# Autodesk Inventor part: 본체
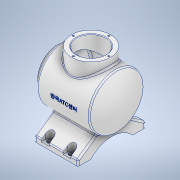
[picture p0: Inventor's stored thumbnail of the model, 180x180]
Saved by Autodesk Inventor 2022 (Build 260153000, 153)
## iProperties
Created: 2023-04
Part Number: 본체
Material: 알루미늄 6061
Document SubType Name: Modeling
Designer: Admin
Mass: 1296.71 g
Surface Area: 1060.44 cm^2
Volume: 480.263 cm^3
Density: 2.7 g/cm^3
Appearance: 알루미늄 - 평지
Author: Admin
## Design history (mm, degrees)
sketch "스케치1"
  geometry: L1 (-84.575, 0)-(87.453, 0) reference; L2 (0, -24.969)-(0, 149.813) reference; L3 (-60, 0)-(-60, 36); L4 (-60, 36)-(-48, 36); L5 (-48, 36)-(-48, 50); L6 (-48, 50)-(48.336, 50); L7 (60, 0)-(60, 124.844); L8 (-60, 0)-(60, 0); A1 r 113 centre (-53, 0) between (60, 0) and (48.336, 50); 1 further point
  constraints: 12 end point, 2 perpendicular, 2 point on circle, 2 point on line, 2 vertical, 1 centre point, 1 collinear, 1 horizontal, 1 tangent, 1 other
  dimensions: "d2" = 226 diameter of A1; "d3" = 120 distance from line of L7.start L3; "d4" = 108 distance from line of L7.start L5; "d5" = 72 diameter of L4 L1; "d6" = 100 diameter of L6 L1
revolve "회전1" sketch "스케치1" stored, may be unused: angle "d7" = 90 deg
node "작업 평면1"
sketch "스케치2"
  geometry: L1 (-38.5, -77)-(-62, -77); L2 (-62, -77)-(-62, -67); L3 (-62, -67)-(-15.04, -34.118); L4 (0, -144.515)-(0, 82.419) reference; L5 (62, -67)-(15.04, -34.118); L6 (62, -77)-(62, -67); L7 (38.5, -77)-(62, -77); L8 (-19.186, -60)-(22.433, -60); L9 (-86.8, 0)-(86.8, 0) reference; L10 (-15.04, -34.118)-(15.04, -34.118); A1 r 52.096 centre (0, -112.096) between (38.5, -77) and (-38.5, -77); 1 further point
  constraints: 16 end point, 4 symmetric about line, 3 horizontal, 2 point on circle, 1 centre point, 1 perpendicular, 1 tangent
  dimensions: "d9" = 10 distance of L1.end L2.end; "d10" = 77 distance of L7.start L1.start; "d11" = 55 deg angle of L6 L5; "d12" = 17 distance between parallel lines of L8 L7; "d13" = 124 distance between parallel lines of L6 L2; "d14" = 77 distance between parallel lines of L7 L9; "d15" = 42.88199 distance between parallel lines of L7 L10
extrude "돌출1" join sketch "스케치2" distance "d16" = 80; taper "d17" = 0 deg
node "작업 평면2"
sketch "스케치3"
  geometry: L1 (-44, -38.5)-(124, -38.5) reference; L2 (-20, -74.5)-(-20, -2.5) reference; C1 r 36 at (42, -38.5); 1 further point
  constraints: 1 centre point, 1 coincident, 1 point on line
  dimensions: "d19" = 72 diameter of C1; "d82" = 62 distance from line of point (42, -38.5) L2
extrude "돌출2" join sketch "스케치3" stored distance "d20" = 80; taper "d21" = 0 deg
sketch "스케치4"
  geometry: C1 r 36 at (0, 0) reference; C2 r 27 at (0, 0); 1 further point
  constraints: 1 centre point, 1 coincident
  dimensions: "d22" = 54 diameter of C2
extrude "돌출3" cut sketch "스케치4" distance "d23" = 60; taper "d24" = 0 deg
sketch "스케치5"
  geometry: L1 (-84, 0)-(84, 0) reference; L2 (-60, -36)-(-60, 36) reference; L3 (-60, 27)-(-41, 27); L4 (-41, 27)-(-41, 43); L5 (-41, 43)-(43.887, 43); L6 (-60, 27)-(-60, 0); L7 (-60, 0)-(53, 0); L8 (48.336, -50)-(48.336, 50) reference; A1 r 113 centre (-53, 0) between (48.336, -50) and (48.336, 50) reference; A2 r 106 centre (-53, 0) between (53, 0) and (43.887, 43); 1 further point
  constraints: 10 end point, 4 perpendicular, 2 point on circle, 2 point on line, 1 centre point, 1 midpoint
  dimensions: "d25" = 7 radial gap between concentric circles of A1 A2; "d26" = 54 diameter of L3 L1; "d27" = 19 distance of L3.start L3.end; "d28" = 86 diameter of L5 L1
revolve "회전2" sketch "스케치5" stored, may be unused: angle "d29" = 90 deg
node "작업 평면3"
sketch "스케치7"
  geometry: L1 (0, 0)-(80, 0) reference; L2 (0, 0)-(0, 23.5) reference; L3 (-44, 62)-(124, 62) reference; C1 r 4.5 at (20, 8); C2 r 4.5 at (60, 8); C3 r 4.5 at (20, 116); C4 r 4.5 at (60, 116); 1 further point
  constraints: 4 centre point, 2 symmetric about line, 2 other
  dimensions: "d37" = 8 distance from line of C1.centre L1; "d38" = 20 distance from line of C1.centre L2; "d39" = 9 diameter of C1; "d40" = 9 diameter of C2; "d41" = 8 distance from line of L1 C2.centre; "d42" = 40 distance of C2.centre C1.centre
extrude "돌출4" cut sketch "스케치7" distance "d43" = 6; taper "d44" = 0 deg
sketch "스케치8"
  geometry: L1 (-7, 0)-(-7, -8); L2 (-20, -8)-(60, -8) reference; L3 (7, 0)-(7, -8); L4 (-7, -8)-(7, -8); L5 (33, 0)-(33, -8); L6 (47, 0)-(47, -8); L7 (33, -8)-(47, -8); L8 (-64, 54)-(104, 54) reference; L9 (-7, -8)-(7, -8); L10 (-7, 108)-(-7, 116); L11 (7, 108)-(7, 116); L12 (33, 108)-(33, 116); L13 (47, 108)-(47, 116); L14 (-7, 116)-(7, 116); L15 (-20, 116)-(60, 116) reference; L16 (33, 116)-(47, 116); C1 r 4.5 at (0, 0) reference; C2 r 4.5 at (40, 0) reference; A1 r 7 centre (0, 0) between (7, 0) and (-7, 0); A2 r 7 centre (40, 0) between (47, 0) and (33, 0); A3 r 7 centre (0, 108) between (-7, 108) and (7, 108); A4 r 7 centre (40, 108) between (33, 108) and (47, 108); 1 further point
  constraints: 26 end point, 10 symmetric about line, 8 point on circle, 5 collinear, 4 centre point, 4 point on line, 4 tangent, 2 coincident, 2 parallel, 1 perpendicular, 1 vertical, 2 other
  dimensions: "d45" = 14 diameter of A1; "d46" = 14 diameter of A2
extrude "돌출5" cut sketch "스케치8" distance "d47" = 30; taper "d48" = 0 deg
sketch "스케치9" dims "d49" = 65
  geometry: L1 (0, -105.4)-(0, 93.4) reference; C1 r 27 at (0, 0) reference; 9 further points
  constraints: 3 coincident, 2 horizontal alignment, 2 vertical alignment, 1 point on line, 19 other
  dimensions: "d52" = 360 deg dimension on point (0, 0) point (0, 32.5) (derived)
hole "구멍1" sketch "스케치9" at (0, 32.5), (-32.5, 0), (0, -32.5), (32.5, 0) diameter "d54" = 3.242; stored, may be unused: countersink angle "d58" = 90 deg, drill point angle "d60" = 118 deg; dims "d55" = 8, "d56" = 4, "d57" = 2, "d59" = 10
fillet "모깎기1" dims "d73" = 3
fillet "모깎기2" dims "d74" = 3
chamfer "모따기1" distance "d75" = 1; stored, may be unused: second distance "d76" = 2, angle "d77" = 45 deg
node "작업 평면4"
sketch "스케치11"
  geometry: L1 (-60, -36)-(-60, 36) reference; L2 (-84, 0)-(84, 0) reference; 2 further points
  constraints: 1 point on line, 1 other
  dimensions: "d79" = 62 distance from line of point (2, 0) L1
feature "엠보싱1" sketch "스케치11" dims "d9" = 10, "d10" = 77, "d11" = 55 deg, "d12" = 17, "d13" = 124, "d14" = 77, "d15" = 42.88199, "d80" = 0.5, "d81" = 0
sketch "스케치12" dims "d83" = 65
  geometry: L1 (0, 0)-(0, 55.021); C1 r 36 at (0, 0) reference; 9 further points
  constraints: 3 coincident, 2 end point, 2 horizontal alignment, 2 vertical alignment, 1 point on line, 1 vertical, 19 other
  dimensions: "d86" = 360 deg dimension on point (0, 0) point (0, 32.5) (derived)
hole "구멍3" sketch "스케치12" at (0, 32.5), (-32.5, 0), (0, -32.5), (32.5, 0) diameter "d88" = 3.242; stored, may be unused: countersink angle "d92" = 90 deg, drill point angle "d94" = 118 deg; dims "d89" = 8, "d90" = 4, "d91" = 2, "d93" = 10
node "솔리드1"
feature "A9D066F2-1C7D-4E18-AEED-F7BC21143FA4" dims "d54" = 3.242, "d55" = 8, "d56" = 4, "d57" = 2, "d58" = 90 deg, "d59" = 10, "d60" = 118 deg
other parameters: "d18" = -142, "d30" = -27.5, "d78" = 136.5
